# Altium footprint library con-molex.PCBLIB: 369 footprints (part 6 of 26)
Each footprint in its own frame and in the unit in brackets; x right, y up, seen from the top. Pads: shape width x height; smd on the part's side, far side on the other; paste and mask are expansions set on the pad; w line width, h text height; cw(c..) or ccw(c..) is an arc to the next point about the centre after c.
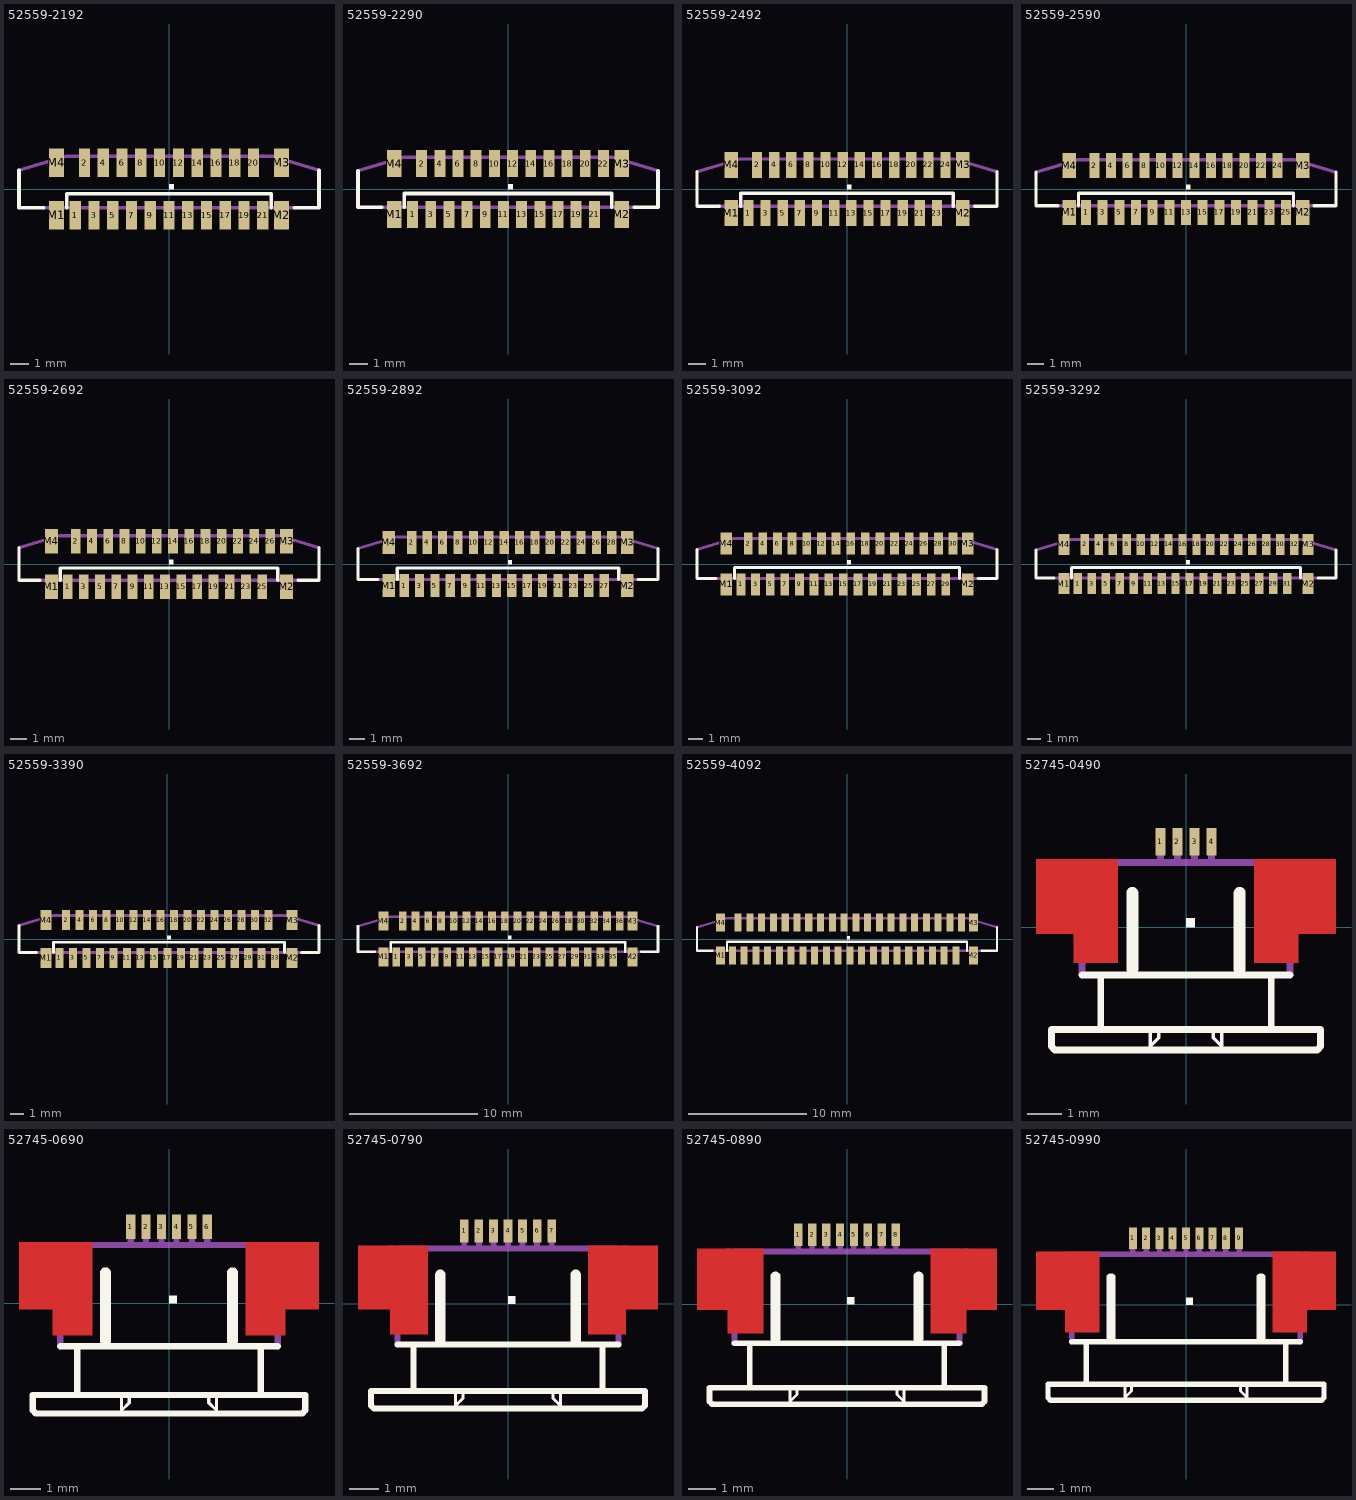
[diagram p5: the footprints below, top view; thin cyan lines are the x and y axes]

## 52559-2192 [mm]
pads (25):
  rect 0.6x1.5 smd: 1(-5,-1.4) 2(-4.5,1.4) 3(-4,-1.4) 4(-3.5,1.4) 5(-3,-1.4) 6(-2.5,1.4) 7(-2,-1.4) 8(-1.5,1.4) 9(-1,-1.4) 10(-0.5,1.4) 11(0,-1.4) 12(0.5,1.4) 13(1,-1.4) 14(1.5,1.4) 15(2,-1.4) 16(2.5,1.4) 17(3,-1.4) 18(3.5,1.4) 19(4,-1.4) 20(4.5,1.4) 21(5,-1.4)
  rect 0.8x1.5 smd: M1(-6,-1.4) M2(6,-1.4) M3(6,1.4) M4(-6,1.4)
Top Overlay:
  region: 0,0 0.254,0 0.254,0.254 0,0.254
  lines w0.203: -8,1 -8,-1 -6.7,-1 ; -5.45,-1 -5.45,-0.25 5.45,-0.25 5.45,-1 ; 6.7,-1 8,-1 8,1
Mechanical 16:
  rectangle: -6.25,-1.55 -5.75,-1.1
  rectangle: -5.15,-1.55 -4.85,-1.1
  rectangle: -4.15,-1.55 -3.85,-1.1
  rectangle: -3.15,-1.55 -2.85,-1.1
  rectangle: 5.75,-1.55 6.25,-1.1
  rectangle: -2.15,-1.55 -1.85,-1.1
  rectangle: -1.15,-1.55 -0.85,-1.1
  rectangle: -0.15,-1.55 0.15,-1.1
  rectangle: 0.85,-1.55 1.15,-1.1
  rectangle: 1.85,-1.55 2.15,-1.1
  rectangle: 2.85,-1.55 3.15,-1.1
  rectangle: 3.85,-1.55 4.15,-1.1
  rectangle: 4.85,-1.55 5.15,-1.1
  lines w0.203: -8,1 -5.5,1.75 5.5,1.75 8,1 ; -6.7,-1 6.7,-1

## 52559-2290 [mil]
pads (26):
  rect 23.62x59.06 smd: 1(-206.69,-55.12) 2(-187.01,55.12) 3(-167.32,-55.12) 4(-147.64,55.12) 5(-127.95,-55.12) 6(-108.27,55.12) 7(-88.58,-55.12) 8(-68.9,55.12) 9(-49.21,-55.12) 10(-29.53,55.12) 11(-9.84,-55.12) 12(9.84,55.12) 13(29.53,-55.12) 14(49.21,55.12) 15(68.9,-55.12) 16(88.58,55.12) 17(108.27,-55.12) 18(127.95,55.12) 19(147.64,-55.12) 20(167.32,55.12) 21(187.01,-55.12) 22(206.69,55.12)
  rect 31.5x59.06 smd: M1(-246.06,-55.12) M2(246.06,-55.12) M3(246.06,55.12) M4(-246.06,55.12)
Top Overlay:
  region: 0,0 10,0 10,10 0,10
  lines w8: -324.8,39.37 -324.8,-39.37 -273.62,-39.37 ; -224.41,-39.37 -224.41,-9.84 224.41,-9.84 224.41,-39.37 ; 273.62,-39.37 324.8,-39.37 324.8,39.37
Mechanical 16:
  rectangle: -255.91,-61.02 -236.22,-43.31
  rectangle: -212.6,-61.02 -200.79,-43.31
  rectangle: -173.23,-61.02 -161.42,-43.31
  rectangle: -133.86,-61.02 -122.05,-43.31
  rectangle: 236.22,-61.02 255.91,-43.31
  rectangle: -94.49,-61.02 -82.68,-43.31
  rectangle: -55.12,-61.02 -43.31,-43.31
  rectangle: -15.75,-61.02 -3.94,-43.31
  rectangle: 23.62,-61.02 35.43,-43.31
  rectangle: 62.99,-61.02 74.8,-43.31
  rectangle: 102.36,-61.02 114.17,-43.31
  rectangle: 141.73,-61.02 153.54,-43.31
  rectangle: 181.1,-61.02 192.91,-43.31
  lines w8: -324.8,39.37 -226.38,68.9 226.38,68.9 324.8,39.37 ; -273.62,-39.37 273.62,-39.37

## 52559-2492 [mil]
pads (28):
  rect 23.62x59.06 smd: 1(-226.38,-55.12) 2(-206.69,55.12) 3(-187.01,-55.12) 4(-167.32,55.12) 5(-147.64,-55.12) 6(-127.95,55.12) 7(-108.27,-55.12) 8(-88.58,55.12) 9(-68.9,-55.12) 10(-49.21,55.12) 11(-29.53,-55.12) 12(-9.84,55.12) 13(9.84,-55.12) 14(29.53,55.12) 15(49.21,-55.12) 16(68.9,55.12) 17(88.58,-55.12) 18(108.27,55.12) 19(127.95,-55.12) 20(147.64,55.12) 21(167.32,-55.12) 22(187.01,55.12) 23(206.69,-55.12) 24(226.38,55.12)
  rect 31.5x59.06 smd: M1(-265.75,-55.12) M2(265.75,-55.12) M3(265.75,55.12) M4(-265.75,55.12)
Top Overlay:
  region: 0,0 10,0 10,10 0,10
  lines w8: -344.49,39.37 -344.49,-39.37 -293.31,-39.37 ; -244.09,-39.37 -244.09,-9.84 244.09,-9.84 244.09,-39.37 ; 293.31,-39.37 344.49,-39.37 344.49,39.37
Mechanical 16:
  rectangle: -275.59,-61.02 -255.91,-43.31
  rectangle: -232.28,-61.02 -220.47,-43.31
  rectangle: -192.91,-61.02 -181.1,-43.31
  rectangle: -153.54,-61.02 -141.73,-43.31
  rectangle: 255.91,-61.02 275.59,-43.31
  rectangle: -114.17,-61.02 -102.36,-43.31
  rectangle: -74.8,-61.02 -62.99,-43.31
  rectangle: -35.43,-61.02 -23.62,-43.31
  rectangle: 3.94,-61.02 15.75,-43.31
  rectangle: 43.31,-61.02 55.12,-43.31
  rectangle: 82.68,-61.02 94.49,-43.31
  rectangle: 122.05,-61.02 133.86,-43.31
  rectangle: 161.42,-61.02 173.23,-43.31
  rectangle: 200.79,-61.02 212.6,-43.31
  lines w8: -344.49,39.37 -246.06,68.9 246.06,68.9 344.49,39.37 ; -293.31,-39.37 293.31,-39.37

## 52559-2590 [mm]
pads (29):
  rect 0.6x1.5 smd: 1(-6,-1.4) 2(-5.5,1.4) 3(-5,-1.4) 4(-4.5,1.4) 5(-4,-1.4) 6(-3.5,1.4) 7(-3,-1.4) 8(-2.5,1.4) 9(-2,-1.4) 10(-1.5,1.4) 11(-1,-1.4) 12(-0.5,1.4) 13(0,-1.4) 14(0.5,1.4) 15(1,-1.4) 16(1.5,1.4) 17(2,-1.4) 18(2.5,1.4) 19(3,-1.4) 20(3.5,1.4) 21(4,-1.4) 22(4.5,1.4) 23(5,-1.4) 24(5.5,1.4) 25(6,-1.4)
  rect 0.8x1.5 smd: M1(-7,-1.4) M2(7,-1.4) M3(7,1.4) M4(-7,1.4)
Top Overlay:
  region: 0,0 0.254,0 0.254,0.254 0,0.254
  lines w0.203: -9,1 -9,-1 -7.7,-1 ; -6.45,-1 -6.45,-0.25 6.45,-0.25 6.45,-1 ; 7.7,-1 9,-1 9,1
Mechanical 16:
  rectangle: -7.25,-1.55 -6.75,-1.1
  rectangle: -6.15,-1.55 -5.85,-1.1
  rectangle: -5.15,-1.55 -4.85,-1.1
  rectangle: -4.15,-1.55 -3.85,-1.1
  rectangle: 6.75,-1.55 7.25,-1.1
  rectangle: -3.15,-1.55 -2.85,-1.1
  rectangle: -2.15,-1.55 -1.85,-1.1
  rectangle: -1.15,-1.55 -0.85,-1.1
  rectangle: -0.15,-1.55 0.15,-1.1
  rectangle: 0.85,-1.55 1.15,-1.1
  rectangle: 1.85,-1.55 2.15,-1.1
  rectangle: 2.85,-1.55 3.15,-1.1
  rectangle: 3.85,-1.55 4.15,-1.1
  rectangle: 4.85,-1.55 5.15,-1.1
  rectangle: 5.85,-1.55 6.15,-1.1
  lines w0.203: -9,1 -6.5,1.75 6.5,1.75 9,1 ; -7.7,-1 7.7,-1

## 52559-2692 [mil]
pads (30):
  rect 23.62x59.06 smd: 1(-246.06,-55.12) 2(-226.38,55.12) 3(-206.69,-55.12) 4(-187.01,55.12) 5(-167.32,-55.12) 6(-147.64,55.12) 7(-127.95,-55.12) 8(-108.27,55.12) 9(-88.58,-55.12) 10(-68.9,55.12) 11(-49.21,-55.12) 12(-29.53,55.12) 13(-9.84,-55.12) 14(9.84,55.12) 15(29.53,-55.12) 16(49.21,55.12) 17(68.9,-55.12) 18(88.58,55.12) 19(108.27,-55.12) 20(127.95,55.12) 21(147.64,-55.12) 22(167.32,55.12) 23(187.01,-55.12) 24(206.69,55.12) 25(226.38,-55.12) 26(246.06,55.12)
  rect 31.5x59.06 smd: M1(-285.43,-55.12) M2(285.43,-55.12) M3(285.43,55.12) M4(-285.43,55.12)
Top Overlay:
  region: 0,0 10,0 10,10 0,10
  lines w8: -364.17,39.37 -364.17,-39.37 -312.99,-39.37 ; -263.78,-39.37 -263.78,-9.84 263.78,-9.84 263.78,-39.37 ; 312.99,-39.37 364.17,-39.37 364.17,39.37
Mechanical 16:
  rectangle: -295.28,-61.02 -275.59,-43.31
  rectangle: -251.97,-61.02 -240.16,-43.31
  rectangle: -212.6,-61.02 -200.79,-43.31
  rectangle: -173.23,-61.02 -161.42,-43.31
  rectangle: 275.59,-61.02 295.28,-43.31
  rectangle: -133.86,-61.02 -122.05,-43.31
  rectangle: -94.49,-61.02 -82.68,-43.31
  rectangle: -55.12,-61.02 -43.31,-43.31
  rectangle: -15.75,-61.02 -3.94,-43.31
  rectangle: 23.62,-61.02 35.43,-43.31
  rectangle: 62.99,-61.02 74.8,-43.31
  rectangle: 102.36,-61.02 114.17,-43.31
  rectangle: 141.73,-61.02 153.54,-43.31
  rectangle: 181.1,-61.02 192.91,-43.31
  rectangle: 220.47,-61.02 232.28,-43.31
  lines w8: -364.17,39.37 -265.75,68.9 265.75,68.9 364.17,39.37 ; -312.99,-39.37 312.99,-39.37

## 52559-2892 [mil]
pads (32):
  rect 23.62x59.06 smd: 1(-265.75,-55.12) 2(-246.06,55.12) 3(-226.38,-55.12) 4(-206.69,55.12) 5(-187.01,-55.12) 6(-167.32,55.12) 7(-147.64,-55.12) 8(-127.95,55.12) 9(-108.27,-55.12) 10(-88.58,55.12) 11(-68.9,-55.12) 12(-49.21,55.12) 13(-29.53,-55.12) 14(-9.84,55.12) 15(9.84,-55.12) 16(29.53,55.12) 17(49.21,-55.12) 18(68.9,55.12) 19(88.58,-55.12) 20(108.27,55.12) 21(127.95,-55.12) 22(147.64,55.12) 23(167.32,-55.12) 24(187.01,55.12) 25(206.69,-55.12) 26(226.38,55.12) 27(246.06,-55.12) 28(265.75,55.12)
  rect 31.5x59.06 smd: M1(-305.12,-55.12) M2(305.12,-55.12) M3(305.12,55.12) M4(-305.12,55.12)
Top Overlay:
  region: 0,0 10,0 10,10 0,10
  lines w8: -383.86,39.37 -383.86,-39.37 -332.68,-39.37 ; -283.46,-39.37 -283.46,-9.84 283.46,-9.84 283.46,-39.37 ; 332.68,-39.37 383.86,-39.37 383.86,39.37
Mechanical 16:
  rectangle: -314.96,-61.02 -295.28,-43.31
  rectangle: -271.65,-61.02 -259.84,-43.31
  rectangle: -232.28,-61.02 -220.47,-43.31
  rectangle: -192.91,-61.02 -181.1,-43.31
  rectangle: 295.28,-61.02 314.96,-43.31
  rectangle: -153.54,-61.02 -141.73,-43.31
  rectangle: -114.17,-61.02 -102.36,-43.31
  rectangle: -74.8,-61.02 -62.99,-43.31
  rectangle: -35.43,-61.02 -23.62,-43.31
  rectangle: 3.94,-61.02 15.75,-43.31
  rectangle: 43.31,-61.02 55.12,-43.31
  rectangle: 82.68,-61.02 94.49,-43.31
  rectangle: 122.05,-61.02 133.86,-43.31
  rectangle: 161.42,-61.02 173.23,-43.31
  rectangle: 200.79,-61.02 212.6,-43.31
  rectangle: 240.16,-61.02 251.97,-43.31
  lines w8: -383.86,39.37 -285.43,68.9 285.43,68.9 383.86,39.37 ; -332.68,-39.37 332.68,-39.37

## 52559-3092 [mil]
pads (34):
  rect 23.62x59.06 smd: 1(-285.43,-55.12) 2(-265.75,55.12) 3(-246.06,-55.12) 4(-226.38,55.12) 5(-206.69,-55.12) 6(-187.01,55.12) 7(-167.32,-55.12) 8(-147.64,55.12) 9(-127.95,-55.12) 10(-108.27,55.12) 11(-88.58,-55.12) 12(-68.9,55.12) 13(-49.21,-55.12) 14(-29.53,55.12) 15(-9.84,-55.12) 16(9.84,55.12) 17(29.53,-55.12) 18(49.21,55.12) 19(68.9,-55.12) 20(88.58,55.12) 21(108.27,-55.12) 22(127.95,55.12) 23(147.64,-55.12) 24(167.32,55.12) 25(187.01,-55.12) 26(206.69,55.12) 27(226.38,-55.12) 28(246.06,55.12) 29(265.75,-55.12) 30(285.43,55.12)
  rect 31.5x59.06 smd: M1(-324.8,-55.12) M2(324.8,-55.12) M3(324.8,55.12) M4(-324.8,55.12)
Top Overlay:
  region: 0,0 10,0 10,10 0,10
  lines w8: -403.54,39.37 -403.54,-39.37 -352.36,-39.37 ; -303.15,-39.37 -303.15,-9.84 303.15,-9.84 303.15,-39.37 ; 352.36,-39.37 403.54,-39.37 403.54,39.37
Mechanical 16:
  rectangle: -334.65,-61.02 -314.96,-43.31
  rectangle: -291.34,-61.02 -279.53,-43.31
  rectangle: -251.97,-61.02 -240.16,-43.31
  rectangle: -212.6,-61.02 -200.79,-43.31
  rectangle: 314.96,-61.02 334.65,-43.31
  rectangle: -173.23,-61.02 -161.42,-43.31
  rectangle: -133.86,-61.02 -122.05,-43.31
  rectangle: -94.49,-61.02 -82.68,-43.31
  rectangle: -55.12,-61.02 -43.31,-43.31
  rectangle: -15.75,-61.02 -3.94,-43.31
  rectangle: 23.62,-61.02 35.43,-43.31
  rectangle: 62.99,-61.02 74.8,-43.31
  rectangle: 102.36,-61.02 114.17,-43.31
  rectangle: 141.73,-61.02 153.54,-43.31
  rectangle: 181.1,-61.02 192.91,-43.31
  rectangle: 220.47,-61.02 232.28,-43.31
  rectangle: 259.84,-61.02 271.65,-43.31
  lines w8: -403.54,39.37 -305.12,68.9 305.12,68.9 403.54,39.37 ; -352.36,-39.37 352.36,-39.37

## 52559-3292 [mil]
pads (36):
  rect 23.62x59.06 smd: 1(-305.12,-55.12) 2(-285.43,55.12) 3(-265.75,-55.12) 4(-246.06,55.12) 5(-226.38,-55.12) 6(-206.69,55.12) 7(-187.01,-55.12) 8(-167.32,55.12) 9(-147.64,-55.12) 10(-127.95,55.12) 11(-108.27,-55.12) 12(-88.58,55.12) 13(-68.9,-55.12) 14(-49.21,55.12) 15(-29.53,-55.12) 16(-9.84,55.12) 17(9.84,-55.12) 18(29.53,55.12) 19(49.21,-55.12) 20(68.9,55.12) 21(88.58,-55.12) 22(108.27,55.12) 23(127.95,-55.12) 24(147.64,55.12) 25(167.32,-55.12) 26(187.01,55.12) 27(206.69,-55.12) 28(226.38,55.12) 29(246.06,-55.12) 30(265.75,55.12) 31(285.43,-55.12) 32(305.12,55.12)
  rect 31.5x59.06 smd: M1(-344.49,-55.12) M2(344.49,-55.12) M3(344.49,55.12) M4(-344.49,55.12)
Top Overlay:
  region: 0,0 10,0 10,10 0,10
  lines w8: -423.23,39.37 -423.23,-39.37 -372.05,-39.37 ; -322.83,-39.37 -322.83,-9.84 322.83,-9.84 322.83,-39.37 ; 372.05,-39.37 423.23,-39.37 423.23,39.37
Mechanical 16:
  rectangle: -354.33,-61.02 -334.65,-43.31
  rectangle: -311.02,-61.02 -299.21,-43.31
  rectangle: -271.65,-61.02 -259.84,-43.31
  rectangle: -232.28,-61.02 -220.47,-43.31
  rectangle: 334.65,-61.02 354.33,-43.31
  rectangle: -192.91,-61.02 -181.1,-43.31
  rectangle: -153.54,-61.02 -141.73,-43.31
  rectangle: -114.17,-61.02 -102.36,-43.31
  rectangle: -74.8,-61.02 -62.99,-43.31
  rectangle: -35.43,-61.02 -23.62,-43.31
  rectangle: 3.94,-61.02 15.75,-43.31
  rectangle: 43.31,-61.02 55.12,-43.31
  rectangle: 82.68,-61.02 94.49,-43.31
  rectangle: 122.05,-61.02 133.86,-43.31
  rectangle: 161.42,-61.02 173.23,-43.31
  rectangle: 200.79,-61.02 212.6,-43.31
  rectangle: 240.16,-61.02 251.97,-43.31
  rectangle: 279.53,-61.02 291.34,-43.31
  lines w8: -423.23,39.37 -324.8,68.9 324.8,68.9 423.23,39.37 ; -372.05,-39.37 372.05,-39.37

## 52559-3390 [mm]
pads (37):
  rect 0.6x1.5 smd: 1(-8,-1.4) 2(-7.5,1.4) 3(-7,-1.4) 4(-6.5,1.4) 5(-6,-1.4) 6(-5.5,1.4) 7(-5,-1.4) 8(-4.5,1.4) 9(-4,-1.4) 10(-3.5,1.4) 11(-3,-1.4) 12(-2.5,1.4) 13(-2,-1.4) 14(-1.5,1.4) 15(-1,-1.4) 16(-0.5,1.4) 17(0,-1.4) 18(0.5,1.4) 19(1,-1.4) 20(1.5,1.4) 21(2,-1.4) 22(2.5,1.4) 23(3,-1.4) 24(3.5,1.4) 25(4,-1.4) 26(4.5,1.4) 27(5,-1.4) 28(5.5,1.4) 29(6,-1.4) 30(6.5,1.4) 31(7,-1.4) 32(7.5,1.4) 33(8,-1.4)
  rect 0.8x1.5 smd: M1(-9,-1.4) M2(9.25,-1.4) M3(9.25,1.4) M4(-9,1.4)
Top Overlay:
  region: 0,0 0.254,0 0.254,0.254 0,0.254
  lines w0.203: -11,1 -11,-1 -9.7,-1 ; -8.45,-1 -8.45,-0.25 8.7,-0.25 8.7,-1 ; 9.95,-1 11.25,-1 11.25,1
Mechanical 16:
  rectangle: -9.25,-1.55 -8.75,-1.1
  rectangle: -8.15,-1.55 -7.85,-1.1
  rectangle: -7.15,-1.55 -6.85,-1.1
  rectangle: -6.15,-1.55 -5.85,-1.1
  rectangle: 9,-1.55 9.5,-1.1
  rectangle: -5.15,-1.55 -4.85,-1.1
  rectangle: -4.15,-1.55 -3.85,-1.1
  rectangle: -3.15,-1.55 -2.85,-1.1
  rectangle: -2.15,-1.55 -1.85,-1.1
  rectangle: -1.15,-1.55 -0.85,-1.1
  rectangle: -0.15,-1.55 0.15,-1.1
  rectangle: 0.85,-1.55 1.15,-1.1
  rectangle: 1.85,-1.55 2.15,-1.1
  rectangle: 2.85,-1.55 3.15,-1.1
  rectangle: 3.85,-1.55 4.15,-1.1
  rectangle: 4.85,-1.55 5.15,-1.1
  rectangle: 5.85,-1.55 6.15,-1.1
  rectangle: 6.85,-1.55 7.15,-1.1
  rectangle: 7.85,-1.55 8.15,-1.1
  lines w0.203: -11,1 -8.5,1.75 8.75,1.75 11.25,1 ; -9.7,-1 9.95,-1

## 52559-3692 [mil]
pads (40):
  rect 23.62x59.06 smd: 1(-344.49,-55.12) 2(-324.8,55.12) 3(-305.12,-55.12) 4(-285.43,55.12) 5(-265.75,-55.12) 6(-246.06,55.12) 7(-226.38,-55.12) 8(-206.69,55.12) 9(-187.01,-55.12) 10(-167.32,55.12) 11(-147.64,-55.12) 12(-127.95,55.12) 13(-108.27,-55.12) 14(-88.58,55.12) 15(-68.9,-55.12) 16(-49.21,55.12) 17(-29.53,-55.12) 18(-9.84,55.12) 19(9.84,-55.12) 20(29.53,55.12) 21(49.21,-55.12) 22(68.9,55.12) 23(88.58,-55.12) 24(108.27,55.12) 25(127.95,-55.12) 26(147.64,55.12) 27(167.32,-55.12) 28(187.01,55.12) 29(206.69,-55.12) 30(226.38,55.12) 31(246.06,-55.12) 32(265.75,55.12) 33(285.43,-55.12) 34(305.12,55.12) 35(324.8,-55.12) 36(344.49,55.12)
  rect 31.5x59.06 smd: M1(-383.86,-55.12) M2(383.86,-55.12) M3(383.86,55.12) M4(-383.86,55.12)
Top Overlay:
  region: 0,0 10,0 10,10 0,10
  lines w8: -462.6,39.37 -462.6,-39.37 -411.42,-39.37 ; -362.2,-39.37 -362.2,-9.84 362.2,-9.84 362.2,-39.37 ; 411.42,-39.37 462.6,-39.37 462.6,39.37
Mechanical 16:
  rectangle: -393.7,-61.02 -374.02,-43.31
  rectangle: -350.39,-61.02 -338.58,-43.31
  rectangle: -311.02,-61.02 -299.21,-43.31
  rectangle: -271.65,-61.02 -259.84,-43.31
  rectangle: 374.02,-61.02 393.7,-43.31
  rectangle: -232.28,-61.02 -220.47,-43.31
  rectangle: -192.91,-61.02 -181.1,-43.31
  rectangle: -153.54,-61.02 -141.73,-43.31
  rectangle: -114.17,-61.02 -102.36,-43.31
  rectangle: -74.8,-61.02 -62.99,-43.31
  rectangle: -35.43,-61.02 -23.62,-43.31
  rectangle: 3.94,-61.02 15.75,-43.31
  rectangle: 43.31,-61.02 55.12,-43.31
  rectangle: 82.68,-61.02 94.49,-43.31
  rectangle: 122.05,-61.02 133.86,-43.31
  rectangle: 161.42,-61.02 173.23,-43.31
  rectangle: 200.79,-61.02 212.6,-43.31
  rectangle: 240.16,-61.02 251.97,-43.31
  rectangle: 279.53,-61.02 291.34,-43.31
  rectangle: 318.9,-61.02 330.71,-43.31
  lines w8: -462.6,39.37 -364.17,68.9 364.17,68.9 462.6,39.37 ; -411.42,-39.37 411.42,-39.37

## 52559-4092 [mil]
pads (44):
  rect 23.62x59.06 smd: 1(-383.86,-55.12) 2(-364.17,55.12) 3(-344.49,-55.12) 4(-324.8,55.12) 5(-305.12,-55.12) 6(-285.43,55.12) 7(-265.75,-55.12) 8(-246.06,55.12) 9(-226.38,-55.12) 10(-206.69,55.12) 11(-187.01,-55.12) 12(-167.32,55.12) 13(-147.64,-55.12) 14(-127.95,55.12) 15(-108.27,-55.12) 16(-88.58,55.12) 17(-68.9,-55.12) 18(-49.21,55.12) 19(-29.53,-55.12) 20(-9.84,55.12) 21(9.84,-55.12) 22(29.53,55.12) 23(49.21,-55.12) 24(68.9,55.12) 25(88.58,-55.12) 26(108.27,55.12) 27(127.95,-55.12) 28(147.64,55.12) 29(167.32,-55.12) 30(187.01,55.12) 31(206.69,-55.12) 32(226.38,55.12) 33(246.06,-55.12) 34(265.75,55.12) 35(285.43,-55.12) 36(305.12,55.12) 37(324.8,-55.12) 38(344.49,55.12) 39(364.17,-55.12) 40(383.86,55.12)
  rect 31.5x59.06 smd: M1(-423.23,-55.12) M2(423.23,-55.12) M3(423.23,55.12) M4(-423.23,55.12)
Top Overlay:
  region: 0,0 10,0 10,10 0,10
  lines w8: -501.97,39.37 -501.97,-39.37 -450.79,-39.37 ; -401.57,-39.37 -401.57,-9.84 401.57,-9.84 401.57,-39.37 ; 450.79,-39.37 501.97,-39.37 501.97,39.37
Mechanical 16:
  rectangle: -433.07,-61.02 -413.39,-43.31
  rectangle: -389.76,-61.02 -377.95,-43.31
  rectangle: -350.39,-61.02 -338.58,-43.31
  rectangle: -311.02,-61.02 -299.21,-43.31
  rectangle: 413.39,-61.02 433.07,-43.31
  rectangle: -271.65,-61.02 -259.84,-43.31
  rectangle: -232.28,-61.02 -220.47,-43.31
  rectangle: -192.91,-61.02 -181.1,-43.31
  rectangle: -153.54,-61.02 -141.73,-43.31
  rectangle: -114.17,-61.02 -102.36,-43.31
  rectangle: -74.8,-61.02 -62.99,-43.31
  rectangle: -35.43,-61.02 -23.62,-43.31
  rectangle: 3.94,-61.02 15.75,-43.31
  rectangle: 43.31,-61.02 55.12,-43.31
  rectangle: 82.68,-61.02 94.49,-43.31
  rectangle: 122.05,-61.02 133.86,-43.31
  rectangle: 161.42,-61.02 173.23,-43.31
  rectangle: 200.79,-61.02 212.6,-43.31
  rectangle: 240.16,-61.02 251.97,-43.31
  rectangle: 279.53,-61.02 291.34,-43.31
  rectangle: 318.9,-61.02 330.71,-43.31
  rectangle: 358.27,-61.02 370.08,-43.31
  lines w8: -501.97,39.37 -403.54,68.9 403.54,68.9 501.97,39.37 ; -450.79,-39.37 450.79,-39.37

## 52745-0490 [mil]
pads (4):
  rect 11.81x31.5 smd: 1(-29.53,98.43) 2(-9.84,98.43) 3(9.84,98.43) 4(29.53,98.43)
Top Layer:
  rectangle: -173.23,-7.87 -78.74,78.74
  rectangle: -129.92,-41.34 -78.74,-7.87
  rectangle: 78.74,-41.34 129.92,-7.87
  rectangle: 78.74,-7.87 173.23,78.74
Top Overlay:
  region: 0,0 10,0 10,10 0,10
  lines w4: -41.34,-122.05 -41.34,-137.8 -31.5,-127.95 -31.5,-122.05 ; 31.5,-122.05 31.5,-127.95 41.34,-137.8 41.34,-122.05
  lines w8: -120.08,-55.12 120.08,-55.12 ; -98.43,-114.17 -98.43,-59.06 ; -64.96,-49.21 -64.96,39.37 cw(c-62.01,39.37) -59.06,39.37 -59.06,-49.21 ; 59.06,-49.21 59.06,39.37 cw(c62.01,39.37) 64.96,39.37 64.96,-49.21 ; 98.43,-114.17 98.43,-59.06 ; -155.51,-137.8 -155.51,-118.11 155.51,-118.11 155.51,-137.8 151.57,-141.73 -151.57,-141.73 -155.51,-137.8
Top Paste:
  region: 165.35,72.83 86.61,72.83 86.61,-1.97 165.35,-1.97
  rectangle: -165.35,-1.97 -86.61,72.83
Top Solder:
  region: 173.23,78.74 127.95,78.74 127.95,-7.87 173.23,-7.87
  region: 129.92,78.74 78.74,78.74 78.74,-41.34 129.92,-41.34
  rectangle: -173.23,-7.87 -127.95,78.74
  rectangle: -129.92,-41.34 -78.74,78.74
Mechanical 16:
  rectangle: -33.46,78.74 -25.59,106.3
  rectangle: -13.78,78.74 -5.91,106.3
  rectangle: 5.91,78.74 13.78,106.3
  rectangle: 25.59,78.74 33.46,106.3
  lines w4: -125.98,74.8 -125.98,27.56 -155.51,27.56 -155.51,35.43 -133.86,35.43 -131.89,37.4 -131.89,57.09 -155.51,57.09 -155.51,64.96 -131.89,64.96 -131.89,76.77 -125.98,76.77 ; 125.98,74.8 125.98,27.56 155.51,27.56 155.51,35.43 133.86,35.43 131.89,37.4 131.89,57.09 155.51,57.09 155.51,64.96 131.89,64.96 131.89,76.77 125.98,76.77
  lines w8: -120.08,-55.12 -120.08,74.8 120.08,74.8 120.08,-55.12

## 52745-0690 [mil]
pads (6):
  rect 11.81x31.5 smd: 1(-49.21,98.43) 2(-29.53,98.43) 3(-9.84,98.43) 4(9.84,98.43) 5(29.53,98.43) 6(49.21,98.43)
Top Layer:
  rectangle: -192.91,-7.87 -98.43,78.74
  rectangle: -149.61,-41.34 -98.43,-7.87
  rectangle: 98.43,-41.34 149.61,-7.87
  rectangle: 98.43,-7.87 192.91,78.74
Top Overlay:
  region: 0,0 10,0 10,10 0,10
  lines w4: -61.02,-122.05 -61.02,-137.8 -51.18,-127.95 -51.18,-122.05 ; 51.18,-122.05 51.18,-127.95 61.02,-137.8 61.02,-122.05
  lines w8: -139.76,-55.12 139.76,-55.12 ; -118.11,-114.17 -118.11,-59.06 ; -84.65,-49.21 -84.65,39.37 cw(c-81.69,39.37) -78.74,39.37 -78.74,-49.21 ; 78.74,-49.21 78.74,39.37 cw(c81.69,39.37) 84.65,39.37 84.65,-49.21 ; 118.11,-114.17 118.11,-59.06 ; -175.2,-137.8 -175.2,-118.11 175.2,-118.11 175.2,-137.8 171.26,-141.73 -171.26,-141.73 -175.2,-137.8
Top Paste:
  region: 185.04,72.83 106.3,72.83 106.3,-1.97 185.04,-1.97
  rectangle: -185.04,-1.97 -106.3,72.83
Top Solder:
  region: 192.91,78.74 147.64,78.74 147.64,-7.87 192.91,-7.87
  region: 149.61,78.74 98.43,78.74 98.43,-41.34 149.61,-41.34
  rectangle: -192.91,-7.87 -147.64,78.74
  rectangle: -149.61,-41.34 -98.43,78.74
Mechanical 16:
  rectangle: -53.15,78.74 -45.28,106.3
  rectangle: -33.46,78.74 -25.59,106.3
  rectangle: -13.78,78.74 -5.91,106.3
  rectangle: 5.91,78.74 13.78,106.3
  rectangle: 25.59,78.74 33.46,106.3
  rectangle: 45.28,78.74 53.15,106.3
  lines w4: -145.67,74.8 -145.67,27.56 -175.2,27.56 -175.2,35.43 -153.54,35.43 -151.57,37.4 -151.57,57.09 -175.2,57.09 -175.2,64.96 -151.57,64.96 -151.57,76.77 -145.67,76.77 ; 145.67,74.8 145.67,27.56 175.2,27.56 175.2,35.43 153.54,35.43 151.57,37.4 151.57,57.09 175.2,57.09 175.2,64.96 151.57,64.96 151.57,76.77 145.67,76.77
  lines w8: -139.76,-55.12 -139.76,74.8 139.76,74.8 139.76,-55.12

## 52745-0790 [mil]
pads (7):
  rect 11.81x31.5 smd: 1(-59.06,98.43) 2(-39.37,98.43) 3(-19.69,98.43) 4(0,98.43) 5(19.69,98.43) 6(39.37,98.43) 7(59.06,98.43)
Top Layer:
  rectangle: -202.76,-7.87 -108.27,78.74
  rectangle: -159.45,-41.34 -108.27,-7.87
  rectangle: 108.27,-41.34 159.45,-7.87
  rectangle: 108.27,-7.87 202.76,78.74
Top Overlay:
  region: 0,0 10,0 10,10 0,10
  lines w4: -70.87,-122.05 -70.87,-137.8 -61.02,-127.95 -61.02,-122.05 ; 61.02,-122.05 61.02,-127.95 70.87,-137.8 70.87,-122.05
  lines w8: -149.61,-55.12 149.61,-55.12 ; -127.95,-114.17 -127.95,-59.06 ; -94.49,-49.21 -94.49,39.37 cw(c-91.53,39.37) -88.58,39.37 -88.58,-49.21 ; 88.58,-49.21 88.58,39.37 cw(c91.53,39.37) 94.49,39.37 94.49,-49.21 ; 127.95,-114.17 127.95,-59.06 ; -185.04,-137.8 -185.04,-118.11 185.04,-118.11 185.04,-137.8 181.1,-141.73 -181.1,-141.73 -185.04,-137.8
Top Paste:
  region: 194.88,72.83 116.14,72.83 116.14,-1.97 194.88,-1.97
  rectangle: -194.88,-1.97 -116.14,72.83
Top Solder:
  region: 202.76,78.74 157.48,78.74 157.48,-7.87 202.76,-7.87
  region: 159.45,78.74 108.27,78.74 108.27,-41.34 159.45,-41.34
  rectangle: -202.76,-7.87 -157.48,78.74
  rectangle: -159.45,-41.34 -108.27,78.74
Mechanical 16:
  rectangle: -62.99,78.74 -55.12,106.3
  rectangle: -43.31,78.74 -35.43,106.3
  rectangle: -23.62,78.74 -15.75,106.3
  rectangle: -3.94,78.74 3.94,106.3
  rectangle: 15.75,78.74 23.62,106.3
  rectangle: 35.43,78.74 43.31,106.3
  rectangle: 55.12,78.74 62.99,106.3
  lines w4: -155.51,74.8 -155.51,27.56 -185.04,27.56 -185.04,35.43 -163.39,35.43 -161.42,37.4 -161.42,57.09 -185.04,57.09 -185.04,64.96 -161.42,64.96 -161.42,76.77 -155.51,76.77 ; 155.51,74.8 155.51,27.56 185.04,27.56 185.04,35.43 163.39,35.43 161.42,37.4 161.42,57.09 185.04,57.09 185.04,64.96 161.42,64.96 161.42,76.77 155.51,76.77
  lines w8: -149.61,-55.12 -149.61,74.8 149.61,74.8 149.61,-55.12

## 52745-0890 [mil]
pads (8):
  rect 11.81x31.5 smd: 1(-68.9,98.43) 2(-49.21,98.43) 3(-29.53,98.43) 4(-9.84,98.43) 5(9.84,98.43) 6(29.53,98.43) 7(49.21,98.43) 8(68.9,98.43)
Top Layer:
  rectangle: -212.6,-7.87 -118.11,78.74
  rectangle: -169.29,-41.34 -118.11,-7.87
  rectangle: 118.11,-41.34 169.29,-7.87
  rectangle: 118.11,-7.87 212.6,78.74
Top Overlay:
  region: 0,0 10,0 10,10 0,10
  lines w4: -80.71,-122.05 -80.71,-137.8 -70.87,-127.95 -70.87,-122.05 ; 70.87,-122.05 70.87,-127.95 80.71,-137.8 80.71,-122.05
  lines w8: -159.45,-55.12 159.45,-55.12 ; -137.8,-114.17 -137.8,-59.06 ; -104.33,-49.21 -104.33,39.37 cw(c-101.38,39.37) -98.43,39.37 -98.43,-49.21 ; 98.43,-49.21 98.43,39.37 cw(c101.38,39.37) 104.33,39.37 104.33,-49.21 ; 137.8,-114.17 137.8,-59.06 ; -194.88,-137.8 -194.88,-118.11 194.88,-118.11 194.88,-137.8 190.94,-141.73 -190.94,-141.73 -194.88,-137.8
Top Paste:
  region: 204.72,72.83 125.98,72.83 125.98,-1.97 204.72,-1.97
  rectangle: -204.72,-1.97 -125.98,72.83
Top Solder:
  region: 212.6,78.74 167.32,78.74 167.32,-7.87 212.6,-7.87
  region: 169.29,78.74 118.11,78.74 118.11,-41.34 169.29,-41.34
  rectangle: -212.6,-7.87 -167.32,78.74
  rectangle: -169.29,-41.34 -118.11,78.74
Mechanical 16:
  rectangle: -72.83,78.74 -64.96,106.3
  rectangle: -53.15,78.74 -45.28,106.3
  rectangle: -33.46,78.74 -25.59,106.3
  rectangle: -13.78,78.74 -5.91,106.3
  rectangle: 5.91,78.74 13.78,106.3
  rectangle: 25.59,78.74 33.46,106.3
  rectangle: 45.28,78.74 53.15,106.3
  rectangle: 64.96,78.74 72.83,106.3
  lines w4: -165.35,74.8 -165.35,27.56 -194.88,27.56 -194.88,35.43 -173.23,35.43 -171.26,37.4 -171.26,57.09 -194.88,57.09 -194.88,64.96 -171.26,64.96 -171.26,76.77 -165.35,76.77 ; 165.35,74.8 165.35,27.56 194.88,27.56 194.88,35.43 173.23,35.43 171.26,37.4 171.26,57.09 194.88,57.09 194.88,64.96 171.26,64.96 171.26,76.77 165.35,76.77
  lines w8: -159.45,-55.12 -159.45,74.8 159.45,74.8 159.45,-55.12

## 52745-0990 [mil]
pads (9):
  rect 11.81x31.5 smd: 1(-78.74,98.43) 2(-59.06,98.43) 3(-39.37,98.43) 4(-19.69,98.43) 5(0,98.43) 6(19.69,98.43) 7(39.37,98.43) 8(59.06,98.43) 9(78.74,98.43)
Top Layer:
  rectangle: -222.44,-7.87 -127.95,78.74
  rectangle: -179.13,-41.34 -127.95,-7.87
  rectangle: 127.95,-41.34 179.13,-7.87
  rectangle: 127.95,-7.87 222.44,78.74
Top Overlay:
  region: 0,0 10,0 10,10 0,10
  lines w4: -90.55,-122.05 -90.55,-137.8 -80.71,-127.95 -80.71,-122.05 ; 80.71,-122.05 80.71,-127.95 90.55,-137.8 90.55,-122.05
  lines w8: -169.29,-55.12 169.29,-55.12 ; -147.64,-114.17 -147.64,-59.06 ; -114.17,-49.21 -114.17,39.37 cw(c-111.22,39.37) -108.27,39.37 -108.27,-49.21 ; 108.27,-49.21 108.27,39.37 cw(c111.22,39.37) 114.17,39.37 114.17,-49.21 ; 147.64,-114.17 147.64,-59.06 ; -204.72,-137.8 -204.72,-118.11 204.72,-118.11 204.72,-137.8 200.79,-141.73 -200.79,-141.73 -204.72,-137.8
Top Paste:
  region: 214.57,72.83 135.83,72.83 135.83,-1.97 214.57,-1.97
  rectangle: -214.57,-1.97 -135.83,72.83
Top Solder:
  region: 222.44,78.74 177.17,78.74 177.17,-7.87 222.44,-7.87
  region: 179.13,78.74 127.95,78.74 127.95,-41.34 179.13,-41.34
  rectangle: -222.44,-7.87 -177.17,78.74
  rectangle: -179.13,-41.34 -127.95,78.74
Mechanical 16:
  rectangle: -82.68,78.74 -74.8,106.3
  rectangle: -62.99,78.74 -55.12,106.3
  rectangle: -43.31,78.74 -35.43,106.3
  rectangle: -23.62,78.74 -15.75,106.3
  rectangle: -3.94,78.74 3.94,106.3
  rectangle: 15.75,78.74 23.62,106.3
  rectangle: 35.43,78.74 43.31,106.3
  rectangle: 55.12,78.74 62.99,106.3
  rectangle: 74.8,78.74 82.68,106.3
  lines w4: -175.2,74.8 -175.2,27.56 -204.72,27.56 -204.72,35.43 -183.07,35.43 -181.1,37.4 -181.1,57.09 -204.72,57.09 -204.72,64.96 -181.1,64.96 -181.1,76.77 -175.2,76.77 ; 175.2,74.8 175.2,27.56 204.72,27.56 204.72,35.43 183.07,35.43 181.1,37.4 181.1,57.09 204.72,57.09 204.72,64.96 181.1,64.96 181.1,76.77 175.2,76.77
  lines w8: -169.29,-55.12 -169.29,74.8 169.29,74.8 169.29,-55.12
